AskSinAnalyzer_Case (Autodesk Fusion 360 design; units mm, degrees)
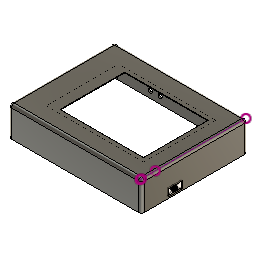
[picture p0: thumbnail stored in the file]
sketch "Front" plane through (0, 0, 0) normal (0, 0, 1) x axis (1, 0, 0)
  line L1 (92.5, 0) -> (0, 0)
  line L2 (92.5, 61.214) -> (92.5, 0)
  line L3 (0, 61.214) -> (92.5, 61.214)
  line L4 (0, 0) -> (0, 61.214)
  line L5 (93, -10) -> (-0.5, -10)
  line L6 (93, 64.214) -> (93, -10)
  line L7 (-0.5, 64.214) -> (93, 64.214)
  line L8 (-0.5, -10) -> (-0.5, 64.214)
  line L9 (81, 3.5) -> (21, 3.5)
  line L10 (81, 50) -> (81, 3.5)
  line L11 (21, 50) -> (81, 50)
  line L12 (21, 3.5) -> (21, 50)
  line L13 (94, -11) -> (-1.5, -11)
  line L14 (94, 65.214) -> (94, -11)
  line L15 (-1.5, 65.214) -> (94, 65.214)
  line L16 (-1.5, -11) -> (-1.5, 65.214)
  line L17 (83.5, 1) -> (13.5, 1)
  line L18 (83.5, 53) -> (83.5, 1)
  line L19 (13.5, 53) -> (83.5, 53)
  line L20 (13.5, 1) -> (13.5, 53)
  line L21 (46.1, 20.15) -> (35.6, 20.15)
  line L22 (46.1, 32.65) -> (46.1, 20.15)
  line L23 (35.6, 32.65) -> (46.1, 32.65)
  line L24 (35.6, 20.15) -> (35.6, 32.65)
  line L25 (46.1, 32.65) -> (35.6, 20.15)
  line L26 (35.6, 32.65) -> (46.1, 20.15)
  line L27 (34.6, 9.35) -> (17.6, 9.35)
  line L28 (34.6, 5.85) -> (34.6, 9.35)
  line L29 (17.6, 5.85) -> (34.6, 5.85)
  line L30 (17.6, 9.35) -> (17.6, 5.85)
  line L31 (34.6, 5.85) -> (17.6, 9.35)
  line L32 (17.6, 5.85) -> (34.6, 9.35)
  circle C1 centre (86.5, 49.6) radius 4
  circle C2 centre (86.5, 5.6) radius 4
  circle C3 centre (10.5, 5.6) radius 4
  circle C4 centre (10.5, 49.6) radius 4
  circle C5 centre (72.15, 56.97) radius 5
  circle C6 centre (41.2, 14.75) radius 2.5
  circle C7 centre (19.1, 14.75) radius 2.5
  point P1 (0, 0)
  point P2 (0, 0)
  point P13 (86.5, 49.6)
  point P26 (86.5, 49.6)
  point P11 (86.5, 5.6)
  point P27 (86.5, 5.6)
  point P10 (10.5, 5.6)
  point P28 (10.5, 5.6)
  point P12 (10.5, 49.6)
  point P29 (10.5, 49.6)
  point P35 (40.85, 26.4)
  point P42 (26.1, 7.6)
  point P4 (92.5, 61.214)
  point P5 (0, 61.214)
  point P14 (21, 3.5)
  point P17 (21, 50)
  point P15 (81, 3.5)
  point P22 (13.5, 1)
  point P25 (13.5, 53)
  point P24 (83.5, 53)
  point P30 (72.15, 56.97)
  point P33 (46.1, 32.65)
  point P34 (35.6, 32.65)
  point P36 (41.2, 14.75)
  point P37 (19.1, 14.75)
  point P40 (34.6, 5.85)
  point P41 (17.6, 5.85)
  point P39 (34.6, 9.35)
  point P3 (92.5, 0)
  horizontal L1
  vertical L2
  horizontal L3
  vertical L4
  coincident P1 P2
  horizontal L5
  vertical L6
  horizontal L7
  vertical L8
  horizontal L9
  vertical L10
  horizontal L11
  vertical L12
  horizontal L17
  vertical L18
  horizontal L19
  vertical L20
  coincident P13 P26
  coincident P11 P27
  coincident P10 P28
  coincident P12 P29
  perpendicular L21 L22
  parallel L21 L23
  parallel L22 L24
  horizontal L21
  coincident L25 P35
  coincident L26 P35
  perpendicular L27 L28
  parallel L27 L29
  parallel L28 L30
  horizontal L27
  coincident L31 P42
  coincident L32 P42
  dimension "d1" distance P4 P5 = 92.5
  dimension "d2" distance P2 P5 = 61.214
  dimension "d3" distance P5 L7 = 3
  dimension "d4" distance P1 L5 = 10
  dimension "d5" distance L4 L8 = 0.5
  dimension "d6" distance L2 L6 = 0.5
  dimension "d7" distance L1 P10 = 5.6
  dimension "d8" distance L4 P10 = 10.5
  dimension "d9" distance L1 P11 = 5.6
  dimension "d10" distance P10 P11 = 76
  dimension "d11" distance L4 P12 = 10.5
  dimension "d12" distance P10 P12 = 44
  dimension "d13" distance P12 P13 = 76
  dimension "d14" distance P11 P13 = 44
  dimension "d15" distance P14 P17 = 46.5
  dimension "d16" distance P14 P15 = 60
  dimension "d17" distance L1 L9 = 3.5
  dimension "d18" distance L4 L12 = 21
  dimension "d19" = 1
  dimension "d24" distance P22 P25 = 52 (= "50 mm + 2 mm")
  dimension "d25" distance P24 P25 = 70 (= "69 mm + 1 mm")
  dimension "d26" distance L11 L19 = 3
  dimension "d30" distance L2 P13 = 6
  dimension "d31" distance L4 L20 = 13.5
  dimension "d32" = 6.5
  dimension "d90" diameter C1 = 8
  dimension "d91" diameter C2 = 8
  dimension "d92" diameter C3 = 8
  dimension "d93" diameter C4 = 8
  dimension "d119" diameter C5 = 10
  dimension "d127" distance P13 P30 = 14.35
  dimension "d128" distance P26 P30 = 7.37
  dimension "d129" distance P33 P34 = 10.5
  dimension "d131" distance P27 P35 = 20.8
  dimension "d132" diameter C6 = 5
  dimension "d133" distance P35 P36 = 11.65
  dimension "d138" distance P10 P35 = 30.35
  dimension "d139" distance P35 P36 = 0.35
  dimension "d140" diameter C7 = 5
  dimension "d141" distance P36 P37 = 22.1
  dimension "d142" distance P40 P41 = 17
  dimension "d143" distance P39 P40 = 3.5
  dimension "d144" distance P10 P42 = 15.6
  dimension "d145" distance P28 P42 = 2
  dimension "d149" distance L21 L23 = 12.5
  dimension "d183" distance P3 = 11.3
extrude "Extrude1" new body sketch "Front" profile of L1 L2 L3 L4 L5 L6 L7 L8 L9 L10 L11 L12 L13 L14 L15 L16 L17 L18 L19 L20 along normal blind 0.5
extrude "Extrude2" add sketch "Front" profile of L5 L6 L7 L8 L13 L14 L15 L16 against normal blind 21
extrude "Extrude3" add sketch "Front" profile of L1 L2 L3 L4 L5 L6 L7 L8 L17 L18 L19 L20 against normal blind 1
cylinder_primitive "CylinderPrimitive1" Height -3.5 Diameter 10
hole "Hole1" HoleDepth 3 HoleDiameter 2.529 TipAngle 180
cylinder_primitive "CylinderPrimitive2" Height -3.5 Diameter 10
hole "Hole2" HoleDepth 3 HoleDiameter 2.529 TipAngle 180
cylinder_primitive "CylinderPrimitive3" Height -3.5 Diameter 10
hole "Hole3" HoleDepth 3 HoleDiameter 2.529 TipAngle 180
cylinder_primitive "CylinderPrimitive4" Height -3.5 Diameter 10
hole "Hole4" HoleDepth 3 HoleDiameter 2.529 TipAngle 180
extrude "Extrude4" cut sketch "Front" profile of L9 L10 L11 L12 L17 L18 L19 L20 against normal blind 4
sketch "Side" plane through (93, 0, 0) normal (-1, 0, 0) x axis (0, -1, 0)
  line L1 (-64.214, -1) -> (10, -1)
  line L2 (-64.214, -21) -> (-64.214, -1)
  line L3 (10, -21) -> (-64.214, -21)
  line L4 (10, -1) -> (10, -21)
  line L5 (-8.5, -20) -> (-18.5, -20)
  line L6 (-8.5, -15) -> (-8.5, -20)
  line L7 (-18.5, -15) -> (-8.5, -15)
  line L8 (-18.5, -20) -> (-18.5, -15)
  line L9 (-8.5, -15) -> (-18.5, -20)
  line L10 (-18.5, -15) -> (-8.5, -20)
  line L11 (-65.214, 0) -> (11, 0)
  point P10 (-13.5, -17.5)
  point P8 (-8.5, -15)
  point P9 (-18.5, -15)
  point P7 (-8.5, -20)
  point P13 (10, 0)
  point P14 (0, 0)
  perpendicular L5 L6
  parallel L5 L7
  parallel L6 L8
  horizontal L5
  coincident L9 P10
  coincident L10 P10
  dimension "d55" distance P8 P9 = 10
  dimension "d56" distance P7 P8 = 5
  dimension "d57" distance P10 L11 = 17.5
  dimension "d58" distance P10 P13 = 23.5 (= "10 mm + 13.5 mm")
  dimension "d59" distance P13 P14 = 10
  dimension "d191" distance L3 L5 = 1
sketch "Top" plane through (0, 64.214, 0) normal (0, -1, 0) x axis (1, 0, 0)
  line L1 (-0.5, -1) -> (93, -1)
  line L2 (-0.5, -21) -> (-0.5, -1)
  line L3 (93, -21) -> (-0.5, -21)
  line L4 (93, -1) -> (93, -21)
  line L5 (64, -5) -> (38, -5)
  line L6 (64, -9) -> (64, -5)
  line L7 (38, -9) -> (64, -9)
  line L8 (38, -5) -> (38, -9)
  line L9 (64, -9) -> (38, -5)
  line L10 (38, -9) -> (64, -5)
  line L11 (-0.5, 0) -> (93, 0)
  circle C1 centre (25.15, -16) radius 1.5
  circle C2 centre (32.25, -16) radius 1.5
  point P13 (51, -7)
  point P6 (25.15, -16)
  point P7 (32.25, -16)
  point P8 (0, 0)
  point P11 (64, -9)
  point P12 (38, -9)
  point P10 (64, -5)
  perpendicular L5 L6
  parallel L5 L7
  parallel L6 L8
  horizontal L5
  coincident L9 P13
  coincident L10 P13
  dimension "d60" diameter C1 = 3
  dimension "d61" diameter C2 = 3
  dimension "d62" distance P6 P7 = 7.1
  dimension "d63" distance P6 P8 = 25.15
  dimension "d64" distance P11 P12 = 26
  dimension "d65" distance P10 P11 = 4
  dimension "d66" distance P8 P13 = 51
  dimension "d67" distance P6 L11 = 16
  dimension "d68" distance P13 L11 = 7
extrude "Extrude5" cut sketch "Top" profile of C1 C2 L5 L6 L7 L8 against normal blind 1
extrude "Extrude6" cut sketch "Side" profile of L5 L6 L7 L8 against normal blind 1
fillet "Fillet1" radius 2
fillet "Fillet2" radius 2
fillet "Fillet3" radius 2
fillet "Fillet4" radius 2
cylinder_primitive "CylinderPrimitive5" Height 9 Diameter 7 bodies "Spacer"
hole "Hole5" HoleDepth 10 HoleDiameter 3.5 TipAngle 180
extrude "Extrude7" sketch "Front" profile of L1 L2 L3 L4 L5 L6 L7 L8 L9 L10 L11 L12 L17 L18 L19 L20 blind 1.5
offset_faces "OffsetFaces1" distance -0.5
offset_faces "OffsetFaces2" distance -0.5
offset_faces "OffsetFaces3" distance -0.5
offset_faces "OffsetFaces4" distance -0.5
fillet "Fillet5" radius 2
extrude "Extrude8" sketch "Front" profile of L18 L20 C1 C2 C3 C4 blind 5 second side blind 0.001
hole "Hole6" HoleDepth 10 HoleDiameter 3.4 TipAngle 180 CBDepth 2 CBDiameter 5.5
hole "Hole7" HoleDepth 10 HoleDiameter 3.5 TipAngle 180 CBDepth 2 CBDiameter 5.5
hole "Hole8" HoleDepth 10 HoleDiameter 3.5 TipAngle 180 CBDepth 2 CBDiameter 5.5
hole "Hole9" HoleDepth 10 HoleDiameter 3.5 TipAngle 180 CBDepth 2 CBDiameter 5.5
extrude "Extrude9" sketch "Front" profile of L1 L17 C5 blind 2
extrude "Extrude10" sketch "Front" profile of L21 L22 L23 L24 C6 blind 2
hole "Hole10" HoleDepth 13.977 HoleDiameter 3.5 TipAngle 180 CSDiameter 5.5 CSAngle 90
hole "Hole11" HoleDepth 13.977 HoleDiameter 3.5 TipAngle 180 CSDiameter 5.5 CSAngle 90
hole "Hole12" HoleDepth 13.977 HoleDiameter 3.5 TipAngle 180 CSDiameter 5.5 CSAngle 90
hole "Hole13" HoleDepth 13.977 HoleDiameter 3.5 TipAngle 180 CSDiameter 5.5 CSAngle 90
sketch "Back" plane through (0, 0, -19.5) normal (0, 0, 1) x axis (-1, 0, 0)
  line L1 (-35.6, -32.65) -> (-35.6, -20.15)
  line L2 (-46.1, -32.65) -> (-35.6, -32.65)
  line L3 (-46.1, -20.15) -> (-46.1, -32.65)
  line L4 (-35.6, -20.15) -> (-46.1, -20.15)
  line L5 (-92.5, -61.714) -> (-92.5, 7.5)
  line L6 (-2, -63.714) -> (-90.5, -63.714)
  line L7 (0, 7.5) -> (0, -61.714)
  line L8 (-90.5, 9.5) -> (-2, 9.5)
  line L9 (-15.1, -10.75) -> (-23.1, -10.75)
  line L10 (-15.1, -18.75) -> (-15.1, -10.75)
  line L11 (-23.1, -18.75) -> (-15.1, -18.75)
  line L12 (-23.1, -10.75) -> (-23.1, -18.75)
  line L13 (-15.1, -18.75) -> (-23.1, -10.75)
  line L14 (-23.1, -18.75) -> (-15.1, -10.75)
  line L15 (-37.2, -10.75) -> (-45.2, -10.75)
  line L16 (-37.2, -18.75) -> (-37.2, -10.75)
  line L17 (-45.2, -18.75) -> (-37.2, -18.75)
  line L18 (-45.2, -10.75) -> (-45.2, -18.75)
  line L19 (-37.2, -18.75) -> (-45.2, -10.75)
  line L20 (-45.2, -18.75) -> (-37.2, -10.75)
  line L21
  line L22 (-26.4, -10.75) -> (-34.4, -10.75)
  line L23 (-26.4, -18.75) -> (-26.4, -10.75)
  line L24 (-34.4, -18.75) -> (-26.4, -18.75)
  line L25 (-34.4, -10.75) -> (-34.4, -18.75)
  line L26 (-26.4, -18.75) -> (-34.4, -10.75)
  line L27 (-34.4, -18.75) -> (-26.4, -10.75)
  circle C1 centre (-41.2, -14.75) radius 2.5
  circle C2 centre (-72.15, -56.97) radius 5
  circle C3 centre (-10.5, -5.6) radius 4
  circle C4 centre (-86.5, -5.6) radius 4
  circle C5 centre (-10.5, -49.6) radius 4
  circle C6 centre (-86.5, -49.6) radius 4
  arc A1 centre (-90.5, 7.5) radius 2 clockwise from (-92.5, 7.5) to (-90.5, 9.5)
  arc A2 centre (-90.5, -61.714) radius 2 clockwise from (-90.5, -63.714) to (-92.5, -61.714)
  arc A3 centre (-2, -61.714) radius 2 clockwise from (0, -61.714) to (-2, -63.714)
  arc A4 centre (-2, 7.5) radius 2 clockwise from (-2, 9.5) to (0, 7.5)
  circle C7 centre (-30.4, -14.75) radius 2.5
  circle C8 centre (-19.1, -14.75) radius 2.5
  point P28 (-19.1, -14.75)
  point P33 (-41.2, -14.75)
  point P6 (-41.2, -14.75)
  point P34 (-19.1, -14.75)
  point P35 (-41.2, -14.75)
  point P36 (-30.4, -14.75)
  point P41 (-30.4, -14.75)
  point P42 (-19.1, -14.75)
  point P25 (-15.1, -10.75)
  point P26 (-15.1, -18.75)
  point P27 (-23.1, -18.75)
  point P31 (-37.2, -18.75)
  point P32 (-45.2, -18.75)
  point P30 (-37.2, -10.75)
  point P38 (-26.4, -10.75)
  point P39 (-26.4, -18.75)
  point P40 (-34.4, -18.75)
  perpendicular L9 L10
  parallel L9 L11
  parallel L10 L12
  horizontal L9
  coincident L13 P28
  coincident L14 P28
  perpendicular L15 L16
  parallel L15 L17
  parallel L16 L18
  horizontal L15
  coincident L19 P33
  coincident L20 P33
  coincident P6 P33
  coincident P28 P34
  coincident P33 P35
  coincident L21 P36
  perpendicular L22 L23
  parallel L22 L24
  parallel L23 L25
  horizontal L22
  coincident L26 P41
  coincident L27 P41
  coincident P36 P41
  coincident P28 P42
  dimension "d170" distance P25 P26 = 8
  dimension "d171" distance P26 P27 = 8
  dimension "d172" distance P31 P32 = 8
  dimension "d173" distance P30 P31 = 8
  dimension "d181" diameter C7 = 5
  dimension "d183" distance P28 P36 = 11.3
  dimension "d184" distance P38 P39 = 8
  dimension "d185" distance P39 P40 = 8
  dimension "d189" diameter C8 = 5
extrude "Extrude16" cut sketch "Back" profile of C8 no distance stored
extrude "Extrude15" cut sketch "Back" profile of C7 L22 L23 L24 L25 against normal blind 1
extrude "Extrude14" cut sketch "Back" profile of C7 no distance stored
extrude "Extrude12" cut sketch "Back" profile of L9 L10 L11 L12 against normal blind 1
extrude "Extrude13" cut sketch "Back" profile of C1 L15 L16 L17 L18 against normal blind 1
offset_faces "OffsetFaces5" distance 15
work_plane "WorkPlane1" RotateAngle -120
split "Split1" bodies "Front (1)"
fillet "Fillet6" radius 2
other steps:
thread "Thread4"
thread "Thread3"
thread "Thread2"
thread "Thread1"
named bodies: "Front", "Spacer", "Back", "Front (1)"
